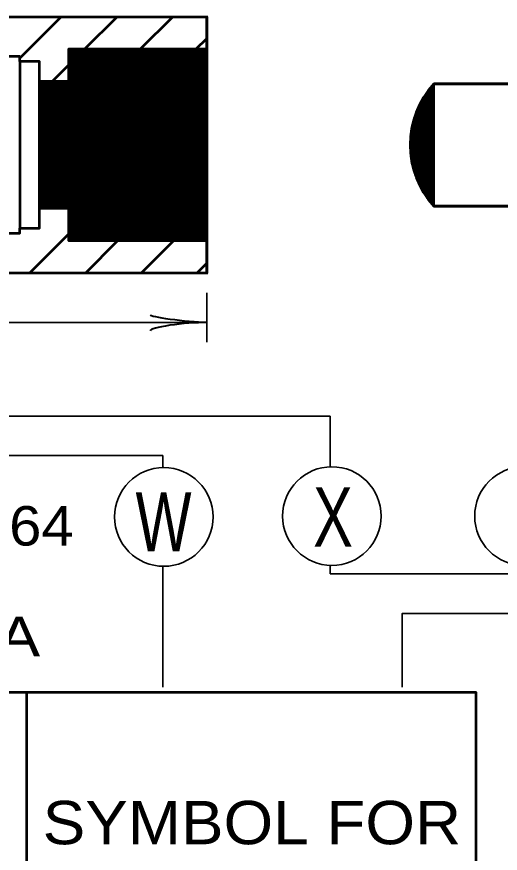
# Model space of a CAD drawing. Extents: x -32 to 824, y -6 to 538.
# Drawn here: x 593.3 to 622.7, y 216.7 to 267.6 of the extents above; entities that cross this region are included whole.
import ezdxf
from ezdxf.enums import TextEntityAlignment as Align

# ---------------------------------------------------------------- set-up
doc = ezdxf.new("R2010")
doc.units = 0
doc.header["$LTSCALE"] = 1.1
doc.layers.add('1', color=7, linetype='Continuous', lineweight=53)

msp = doc.modelspace()

# ---------------------------------------------------------------- linework, layer by layer
at = {"layer": '1'}
for p, q in [((593.469, 265.107), (595.995, 267.633)), ((597.427, 265.67), (599.39, 267.633)), ((600.821, 265.67), (602.784, 267.633)), ((604.858, 267.633), (604.906, 267.633)), ((604.215, 265.67), (604.858, 266.313)), ((594.669, 261.821), (598.518, 265.67)), ((594.669, 261.651), (598.688, 265.67)), ((594.669, 261.482), (598.858, 265.67)), ((594.669, 261.312), (599.027, 265.67)), ((594.669, 261.142), (599.197, 265.67)), ((594.669, 260.972), (599.367, 265.67)), ((594.669, 260.803), (599.536, 265.67)), ((594.669, 260.633), (599.706, 265.67)), ((594.669, 260.463), (599.876, 265.67)), ((594.669, 260.294), (600.046, 265.67)), ((594.669, 260.124), (600.215, 265.67)), ((594.669, 259.954), (600.385, 265.67)), ((594.669, 259.785), (600.555, 265.67)), ((594.669, 259.615), (600.724, 265.67)), ((594.669, 259.445), (600.894, 265.67)), ((594.669, 259.275), (601.064, 265.67)), ((594.669, 259.106), (601.233, 265.67)), ((594.669, 258.936), (601.403, 265.67)), ((594.669, 258.766), (601.573, 265.67)), ((594.669, 258.597), (601.743, 265.67)), ((594.669, 258.427), (601.912, 265.67)), ((594.669, 258.257), (602.082, 265.67)), ((594.669, 258.087), (602.252, 265.67)), ((594.669, 257.918), (602.421, 265.67)), ((594.669, 257.748), (602.591, 265.67)), ((594.669, 257.578), (602.761, 265.67)), ((594.669, 257.409), (602.931, 265.67)), ((594.669, 257.239), (603.1, 265.67)), ((594.669, 257.069), (603.27, 265.67)), ((594.669, 256.899), (603.44, 265.67)), ((594.669, 256.73), (603.609, 265.67)), ((594.669, 256.56), (603.779, 265.67)), ((594.669, 256.39), (603.949, 265.67)), ((594.669, 256.221), (604.118, 265.67)), ((594.669, 256.051), (604.288, 265.67)), ((594.747, 255.959), (604.458, 265.67)), ((594.917, 255.959), (604.628, 265.67)), ((595.087, 255.959), (604.797, 265.67)), ((595.256, 255.959), (604.858, 265.561)), ((595.426, 255.959), (604.858, 265.391)), ((595.596, 255.959), (604.858, 265.221)), ((596.458, 265.646), (596.482, 265.67)), ((596.458, 265.476), (596.651, 265.67)), ((596.458, 265.307), (596.821, 265.67)), ((596.458, 265.137), (596.991, 265.67)), ((596.458, 264.967), (597.161, 265.67)), ((596.458, 264.798), (597.33, 265.67)), ((596.458, 264.628), (597.5, 265.67)), ((596.458, 264.458), (597.67, 265.67)), ((596.458, 264.289), (597.839, 265.67)), ((596.458, 264.119), (598.009, 265.67)), ((596.458, 263.949), (598.179, 265.67)), ((596.458, 263.779), (598.348, 265.67)), ((604.858, 257.103), (596.458, 265.503)), ((604.858, 256.933), (596.458, 265.333)), ((604.858, 257.273), (596.461, 265.67)), ((604.858, 257.442), (596.63, 265.67)), ((604.858, 257.612), (596.8, 265.67)), ((604.858, 257.782), (596.97, 265.67)), ((604.858, 257.952), (597.139, 265.67)), ((604.858, 258.121), (597.309, 265.67)), ((604.858, 258.291), (597.479, 265.67)), ((604.858, 258.461), (597.649, 265.67)), ((604.858, 258.63), (597.818, 265.67)), ((604.858, 258.8), (597.988, 265.67)), ((604.858, 258.97), (598.158, 265.67)), ((604.858, 259.139), (598.327, 265.67)), ((604.858, 259.309), (598.497, 265.67)), ((604.858, 259.479), (598.667, 265.67)), ((604.858, 259.649), (598.836, 265.67)), ((604.858, 259.818), (599.006, 265.67)), ((604.858, 259.988), (599.176, 265.67)), ((604.858, 260.158), (599.346, 265.67)), ((604.858, 260.327), (599.515, 265.67)), ((604.858, 260.497), (599.685, 265.67)), ((604.858, 260.667), (599.855, 265.67)), ((604.858, 260.837), (600.024, 265.67)), ((604.858, 261.006), (600.194, 265.67)), ((604.858, 261.176), (600.364, 265.67)), ((604.858, 261.346), (600.534, 265.67)), ((604.858, 261.515), (600.703, 265.67)), ((604.858, 261.685), (600.873, 265.67)), ((604.858, 261.855), (601.043, 265.67)), ((604.858, 262.024), (601.212, 265.67)), ((604.858, 262.194), (601.382, 265.67)), ((604.858, 262.364), (601.552, 265.67)), ((604.858, 262.534), (601.721, 265.67)), ((604.858, 262.703), (601.891, 265.67)), ((604.858, 262.873), (602.061, 265.67)), ((604.858, 263.043), (602.231, 265.67)), ((604.858, 263.212), (602.4, 265.67)), ((604.858, 263.382), (602.57, 265.67)), ((604.858, 263.552), (602.74, 265.67)), ((604.858, 263.721), (602.909, 265.67)), ((604.858, 263.891), (603.079, 265.67)), ((604.858, 264.061), (603.249, 265.67)), ((604.858, 264.231), (603.418, 265.67)), ((604.858, 264.4), (603.588, 265.67)), ((604.858, 264.57), (603.758, 265.67)), ((604.858, 264.74), (603.928, 265.67)), ((604.858, 264.909), (604.097, 265.67)), ((604.858, 265.079), (604.267, 265.67)), ((604.858, 265.249), (604.437, 265.67)), ((604.858, 265.418), (604.606, 265.67)), ((604.858, 265.588), (604.776, 265.67)), ((593.469, 264.907), (593.469, 254.759)), ((595.463, 263.707), (596.458, 264.701)), ((595.765, 255.959), (604.858, 265.052)), ((595.935, 255.959), (604.858, 264.882)), ((596.105, 255.959), (604.858, 264.712)), ((604.858, 256.764), (596.458, 265.163)), ((604.858, 256.594), (596.458, 264.994)), ((604.858, 256.424), (596.458, 264.824)), ((596.274, 255.959), (604.858, 264.543)), ((596.444, 255.959), (604.858, 264.373)), ((604.858, 256.254), (596.458, 264.654)), ((604.858, 256.085), (596.458, 264.485)), ((604.858, 255.915), (596.458, 264.315)), ((596.458, 255.803), (604.858, 264.203)), ((594.669, 263.688), (594.688, 263.707)), ((594.669, 263.518), (594.858, 263.707)), ((594.669, 263.348), (595.028, 263.707)), ((594.669, 263.179), (595.197, 263.707)), ((594.669, 263.009), (595.367, 263.707)), ((594.669, 262.839), (595.537, 263.707)), ((594.669, 262.67), (595.707, 263.707)), ((594.669, 262.5), (595.876, 263.707)), ((594.669, 262.33), (596.046, 263.707)), ((594.669, 262.16), (596.216, 263.707)), ((594.669, 261.991), (596.385, 263.707)), ((604.401, 253.996), (594.69, 263.707)), ((604.571, 253.996), (594.86, 263.707)), ((604.74, 253.996), (595.029, 263.707)), ((604.858, 254.048), (595.199, 263.707)), ((604.858, 254.218), (595.369, 263.707)), ((604.858, 254.388), (595.539, 263.707)), ((604.858, 254.557), (595.708, 263.707)), ((604.858, 254.727), (595.878, 263.707)), ((604.858, 254.897), (596.048, 263.707)), ((604.858, 255.067), (596.217, 263.707)), ((604.858, 255.236), (596.387, 263.707)), ((604.858, 255.745), (596.458, 264.145)), ((596.458, 255.634), (604.858, 264.034)), ((604.858, 255.576), (596.458, 263.976)), ((596.458, 255.464), (604.858, 263.864)), ((604.858, 255.406), (596.458, 263.806)), ((596.458, 255.294), (604.858, 263.694)), ((604.231, 253.996), (594.669, 263.558)), ((604.061, 253.996), (594.669, 263.389)), ((603.892, 253.996), (594.669, 263.219)), ((596.458, 255.125), (604.858, 263.524)), ((596.458, 254.955), (604.858, 263.355)), ((596.458, 254.785), (604.858, 263.185)), ((617.837, 262.344), (618.669, 263.175)), ((618.048, 262.724), (618.669, 263.345)), ((618.669, 262.827), (618.34, 263.156)), ((618.669, 262.997), (618.417, 263.249)), ((618.476, 263.322), (618.669, 263.515)), ((618.669, 263.167), (618.493, 263.343)), ((618.669, 263.336), (618.57, 263.436)), ((618.669, 263.506), (618.646, 263.529)), ((618.669, 256.109), (618.669, 263.557)), ((624.369, 263.557), (618.669, 263.557)), ((618.669, 263.557), (623.631, 263.557)), ((603.722, 253.996), (594.669, 263.049)), ((603.552, 253.996), (594.669, 262.879)), ((603.383, 253.996), (594.669, 262.71)), ((596.458, 254.615), (604.858, 263.015)), ((596.458, 254.446), (604.858, 262.846)), ((596.458, 254.276), (604.858, 262.676)), ((617.481, 261.478), (618.669, 262.666)), ((617.571, 261.738), (618.669, 262.836)), ((617.681, 262.017), (618.669, 263.006)), ((618.669, 261.979), (617.999, 262.649)), ((618.669, 262.149), (618.066, 262.751)), ((618.669, 262.318), (618.134, 262.854)), ((618.669, 262.488), (618.201, 262.956)), ((618.669, 262.658), (618.268, 263.058)), ((603.213, 253.996), (594.669, 262.54)), ((603.043, 253.996), (594.669, 262.37)), ((602.874, 253.996), (594.669, 262.201)), ((596.458, 254.106), (604.858, 262.506)), ((596.518, 253.996), (604.858, 262.337)), ((596.687, 253.996), (604.858, 262.167)), ((617.319, 260.807), (618.669, 262.157)), ((617.353, 261.011), (618.669, 262.327)), ((617.416, 261.244), (618.669, 262.497)), ((618.669, 261.3), (617.765, 262.204)), ((618.669, 261.47), (617.823, 262.316)), ((618.669, 261.639), (617.881, 262.428)), ((618.669, 261.809), (617.939, 262.539)), ((602.704, 253.996), (594.669, 262.031)), ((602.534, 253.996), (594.669, 261.861)), ((602.364, 253.996), (594.669, 261.692)), ((596.857, 253.996), (604.858, 261.997)), ((597.027, 253.996), (604.858, 261.827)), ((597.196, 253.996), (604.858, 261.658)), ((617.247, 260.226), (618.669, 261.648)), ((617.258, 260.406), (618.669, 261.818)), ((617.286, 260.604), (618.669, 261.987)), ((618.669, 260.621), (617.566, 261.724)), ((618.669, 260.791), (617.614, 261.846)), ((618.669, 260.961), (617.661, 261.968)), ((618.669, 261.13), (617.709, 262.09)), ((602.195, 253.996), (594.669, 261.522)), ((602.025, 253.996), (594.669, 261.352)), ((601.855, 253.996), (594.669, 261.182)), ((597.366, 253.996), (604.858, 261.488)), ((597.536, 253.996), (604.858, 261.318)), ((597.706, 253.996), (604.858, 261.149)), ((617.226, 259.865), (618.669, 261.309)), ((617.233, 259.703), (618.669, 261.139)), ((617.236, 260.045), (618.669, 261.478)), ((618.669, 259.942), (617.406, 261.206)), ((618.669, 260.112), (617.442, 261.339)), ((618.669, 260.282), (617.479, 261.472)), ((618.669, 260.451), (617.518, 261.602)), ((601.686, 253.996), (594.669, 261.013)), ((601.516, 253.996), (594.669, 260.843)), ((601.346, 253.996), (594.669, 260.673)), ((597.875, 253.996), (604.858, 260.979)), ((598.045, 253.996), (604.858, 260.809)), ((598.215, 253.996), (604.858, 260.639)), ((617.241, 259.541), (618.669, 260.969)), ((617.248, 259.379), (618.669, 260.8)), ((617.263, 259.223), (618.669, 260.63)), ((618.669, 259.264), (617.292, 260.641)), ((618.669, 259.433), (617.316, 260.786)), ((618.669, 259.603), (617.34, 260.932)), ((618.669, 259.773), (617.369, 261.072)), ((601.176, 253.996), (594.669, 260.504)), ((601.007, 253.996), (594.669, 260.334)), ((600.837, 253.996), (594.669, 260.164)), ((598.384, 253.996), (604.858, 260.47)), ((598.554, 253.996), (604.858, 260.3)), ((598.724, 253.996), (604.858, 260.13)), ((618.669, 258.754), (617.244, 260.179)), ((618.669, 258.924), (617.254, 260.34)), ((618.669, 259.094), (617.268, 260.495)), ((617.285, 259.076), (618.669, 260.46)), ((617.307, 258.929), (618.669, 260.29)), ((617.33, 258.781), (618.669, 260.121)), ((600.667, 253.996), (594.669, 259.994)), ((600.498, 253.996), (594.669, 259.825)), ((600.328, 253.996), (594.669, 259.655)), ((598.893, 253.996), (604.858, 259.961)), ((599.063, 253.996), (604.858, 259.791)), ((599.233, 253.996), (604.858, 259.621)), ((618.669, 258.415), (617.226, 259.858)), ((618.669, 258.585), (617.235, 260.019)), ((618.669, 258.245), (617.235, 259.68)), ((617.36, 258.641), (618.669, 259.951)), ((617.395, 258.507), (618.669, 259.781)), ((617.43, 258.372), (618.669, 259.612)), ((600.158, 253.996), (594.669, 259.485)), ((599.989, 253.996), (594.669, 259.316)), ((599.819, 253.996), (594.669, 259.146)), ((599.403, 253.996), (604.858, 259.452)), ((599.572, 253.996), (604.858, 259.282)), ((599.742, 253.996), (604.858, 259.112)), ((618.669, 258.076), (617.243, 259.502)), ((618.669, 257.906), (617.251, 259.324)), ((618.669, 257.736), (617.277, 259.128)), ((617.465, 258.238), (618.669, 259.442)), ((617.505, 258.108), (618.669, 259.272)), ((617.551, 257.985), (618.669, 259.102)), ((599.649, 253.996), (594.669, 258.976)), ((599.479, 253.996), (594.669, 258.807)), ((599.31, 253.996), (594.669, 258.637)), ((599.912, 253.996), (604.858, 258.942)), ((600.081, 253.996), (604.858, 258.773)), ((600.251, 253.996), (604.858, 258.603)), ((618.669, 257.566), (617.307, 258.928)), ((618.669, 257.397), (617.338, 258.728)), ((617.598, 257.861), (618.669, 258.933)), ((617.644, 257.738), (618.669, 258.763)), ((617.691, 257.615), (618.669, 258.593)), ((599.14, 253.996), (594.669, 258.467)), ((598.97, 253.996), (594.669, 258.297)), ((598.801, 253.996), (594.669, 258.128)), ((600.421, 253.996), (604.858, 258.433)), ((600.591, 253.996), (604.858, 258.264)), ((600.76, 253.996), (604.858, 258.094)), ((618.669, 257.227), (617.397, 258.5)), ((618.669, 257.057), (617.456, 258.27)), ((617.747, 257.502), (618.669, 258.424)), ((617.804, 257.389), (618.669, 258.254)), ((617.861, 257.276), (618.669, 258.084)), ((598.631, 253.996), (594.669, 257.958)), ((598.461, 253.996), (594.669, 257.788)), ((596.328, 255.959), (594.669, 257.619)), ((600.93, 253.996), (604.858, 257.924)), ((601.1, 253.996), (604.858, 257.755)), ((601.269, 253.996), (604.858, 257.585)), ((618.669, 256.888), (617.538, 258.018)), ((618.669, 256.718), (617.641, 257.746)), ((617.917, 257.163), (618.669, 257.915)), ((617.979, 257.054), (618.669, 257.745)), ((618.045, 256.951), (618.669, 257.575)), ((596.159, 255.959), (594.669, 257.449)), ((595.989, 255.959), (594.669, 257.279)), ((595.819, 255.959), (594.669, 257.109)), ((601.439, 253.996), (604.858, 257.415)), ((601.609, 253.996), (604.858, 257.245)), ((601.778, 253.996), (604.858, 257.076)), ((618.669, 256.548), (617.78, 257.438)), ((618.669, 256.379), (617.952, 257.096)), ((618.111, 256.847), (618.669, 257.405)), ((618.177, 256.744), (618.669, 257.236)), ((618.243, 256.64), (618.669, 257.066)), ((595.649, 255.959), (594.669, 256.94)), ((595.48, 255.959), (594.669, 256.77)), ((595.31, 255.959), (594.669, 256.6)), ((601.948, 253.996), (604.858, 256.906)), ((602.118, 253.996), (604.858, 256.736)), ((602.288, 253.996), (604.858, 256.567)), ((618.669, 256.209), (618.254, 256.624)), ((618.317, 256.544), (618.669, 256.896)), ((618.392, 256.449), (618.669, 256.726)), ((618.467, 256.355), (618.669, 256.557)), ((595.14, 255.959), (594.669, 256.431)), ((594.971, 255.959), (594.669, 256.261)), ((594.801, 255.959), (594.669, 256.091)), ((602.457, 253.996), (604.858, 256.397)), ((602.627, 253.996), (604.858, 256.227)), ((602.797, 253.996), (604.858, 256.057)), ((618.543, 256.261), (618.669, 256.387)), ((618.618, 256.166), (618.669, 256.217)), ((596.458, 253.996), (596.458, 255.959)), ((598.291, 253.996), (596.458, 255.83)), ((598.122, 253.996), (596.458, 255.66)), ((602.966, 253.996), (604.858, 255.888)), ((603.136, 253.996), (604.858, 255.718)), ((603.306, 253.996), (604.858, 255.548)), ((597.952, 253.996), (596.458, 255.49)), ((597.782, 253.996), (596.458, 255.321)), ((597.613, 253.996), (596.458, 255.151)), ((603.476, 253.996), (604.858, 255.379)), ((603.645, 253.996), (604.858, 255.209)), ((603.815, 253.996), (604.858, 255.039)), ((597.443, 253.996), (596.458, 254.981)), ((597.273, 253.996), (596.458, 254.812)), ((597.104, 253.996), (596.458, 254.642)), ((603.985, 253.996), (604.858, 254.87)), ((604.154, 253.996), (604.858, 254.7)), ((604.324, 253.996), (604.858, 254.53)), ((594.07, 252.033), (596.458, 254.421)), ((596.934, 253.996), (596.458, 254.472)), ((596.764, 253.996), (596.458, 254.302)), ((596.594, 253.996), (596.458, 254.133)), ((597.465, 252.033), (599.428, 253.996)), ((600.859, 252.033), (602.822, 253.996)), ((604.494, 253.996), (604.858, 254.36)), ((604.663, 253.996), (604.858, 254.191)), ((604.833, 253.996), (604.858, 254.021)), ((604.253, 252.033), (604.858, 252.638)), ((604.906, 252.033), (604.858, 252.033)), ((593.887, 226.546), (593.887, 173.746))]:
    msp.add_line(p, q, dxfattribs=at)
at = {"layer": '1', "lineweight": 35}
for p, q in [((604.858, 250.833), (604.858, 247.833)), ((564.058, 249.033), (604.858, 249.033)), ((547.258, 243.333), (612.361, 243.333)), ((612.361, 243.333), (612.361, 240.25)), ((560.458, 240.933), (602.179, 240.933)), ((602.179, 240.933), (602.179, 240.198)), ((602.179, 234.199), (602.179, 226.837)), ((612.361, 234.254), (612.361, 233.733)), ((612.361, 233.733), (673.125, 233.733))]:
    msp.add_line(p, q, dxfattribs=at)
at = {"layer": '1'}
for points in [[(564.058, 261.633), (564.058, 264.633), (573.658, 264.633), (580.858, 266.733), (580.858, 267.633), (604.858, 267.633), (604.858, 265.67)], [(596.458, 263.707), (596.458, 265.67), (604.858, 265.67), (604.858, 267.633)], [(594.669, 263.707), (594.669, 264.907), (593.469, 264.907), (593.469, 265.207), (592.269, 265.207), (592.269, 264.307), (588.069, 264.307)], [(624.369, 256.109), (618.669, 256.109), (623.226, 256.109)], [(588.069, 255.359), (592.269, 255.359), (592.269, 254.459), (593.469, 254.459), (593.469, 254.759), (594.669, 254.759), (594.669, 255.959)], [(604.858, 253.996), (604.858, 252.033), (580.858, 252.033), (580.858, 252.933), (573.658, 255.033), (564.058, 255.033)], [(604.858, 252.033), (604.858, 253.996), (596.458, 253.996)], [(554.287, 226.546), (621.227, 226.546), (621.227, 173.746)]]:
    msp.add_lwpolyline(points, dxfattribs=at)
msp.add_lwpolyline([(594.669, 263.707), (596.458, 263.707), (596.458, 265.67), (604.858, 265.67), (604.858, 253.996), (596.458, 253.996), (596.458, 255.959), (594.669, 255.959)], close=True, dxfattribs=at)
at = {"layer": '1', "lineweight": 35}
msp.add_lwpolyline([(624.058, 231.333), (616.741, 231.333), (616.741, 226.837)], dxfattribs=at)
for centre in [(612.465, 237.252), (624.153, 237.252), (602.236, 237.198)]:
    msp.add_circle(centre, 3, dxfattribs=at)
at = {"layer": '1'}
msp.add_arc((622.751, 259.833), 5.525, 137.6256, 222.3744, dxfattribs=at)
at = {"layer": '1', "lineweight": 40}
for centre, major_axis, ratio, start_param, end_param in [((603.513, 249.287), (2.108, -0.211), 0.07063, 3.140715, 5.41811), ((603.548, 248.702), (2.143, 0.187), 0.122415, 0.896353, 3.141593)]:
    msp.add_ellipse(centre, major_axis=major_axis, ratio=ratio, start_param=start_param, end_param=end_param, dxfattribs=at)

# ---------------------------------------------------------------- texts
at = {"layer": '1'}
for s, height, width, p in [('X', 3.6, 0.75, (611.326, 235.4)), ('W', 3.6, 0.75, (600.517, 235.105)), ('ORDERING SYMBOLS: 64', 2.4, 1.1, (553.789, 235.459)), ('TABLE A', 2.4, 1.2, (578.867, 228.728))]:
    msp.add_text(s, height=height, dxfattribs=dict(at, width=width)).set_placement(p)
at = {"layer": '1', "width": 1.1}
msp.add_text('SYMBOL FOR', height=2.64, dxfattribs=at).set_placement((607.597, 217.284), align=Align.CENTER)

doc.saveas('drawing.dxf')
